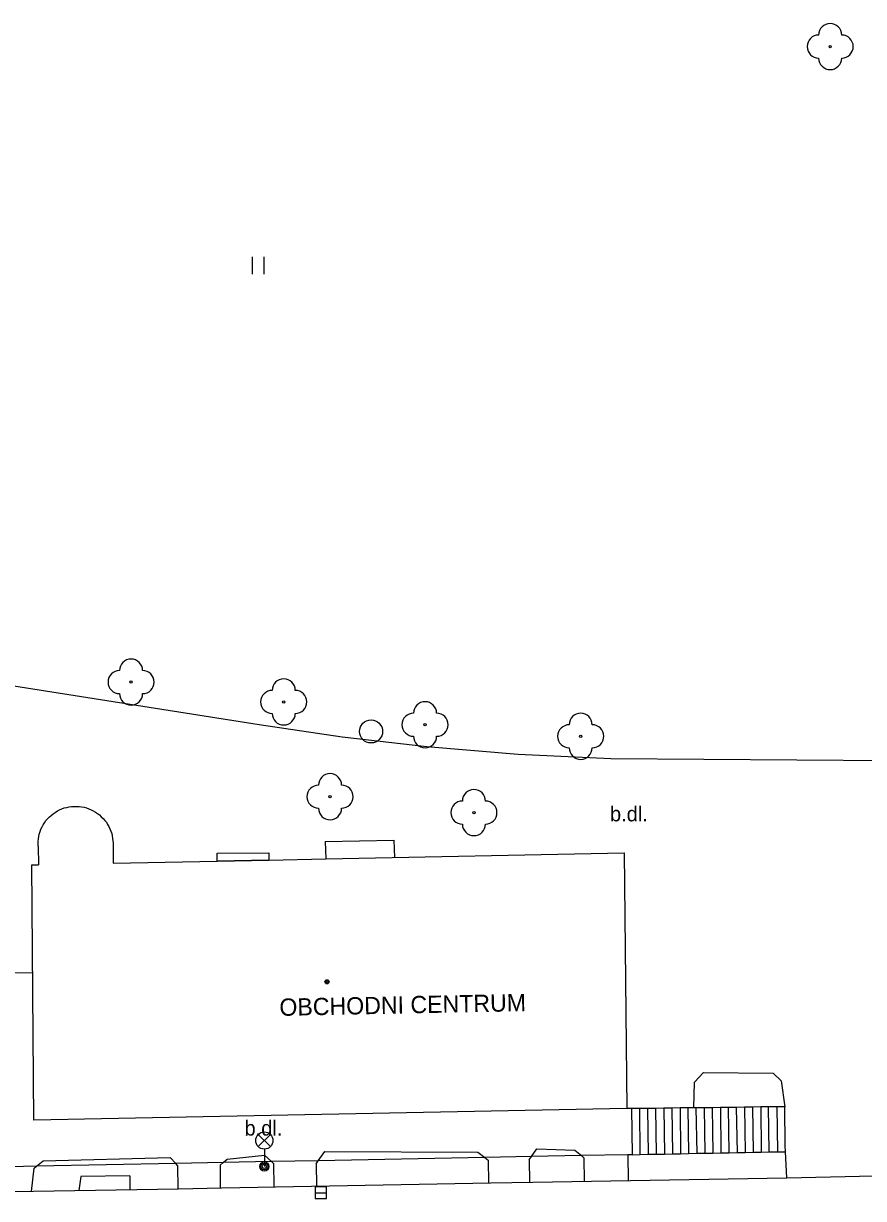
# Model space of a CAD drawing. Extents: x -641829 to -641525, y -1114855 to -1114359.
# Drawn here: x -641633.2 to -641596.7, y -1114670.9 to -1114619.9 of the extents above; entities that cross this region are included whole.
import ezdxf

# ---------------------------------------------------------------- set-up
doc = ezdxf.new("R2010")
doc.units = 0
for name, color, linetype in [('Vrstva 11', 7, 'Continuous'), ('Vrstva 22', 7, 'Continuous'), ('Vrstva 24', 7, 'Continuous'), ('Vrstva 27', 7, 'Continuous'), ('Vrstva 33', 7, 'Continuous'), ('Vrstva 36', 7, 'Continuous'), ('Vrstva 39', 7, 'Continuous'), ('Vrstva 40', 7, 'Continuous'), ('Vrstva 41', 7, 'Continuous'), ('Vrstva 5', 7, 'Continuous')]:
    doc.layers.add(name, color=color, linetype=linetype)

msp = doc.modelspace()

# ---------------------------------------------------------------- linework, layer by layer
at = {"layer": 'Vrstva 11'}
for p, q in [((-641622.94, -1114650.3), (-641619.35, -1114650.84)), ((-641619.35, -1114650.84), (-641615.67, -1114651.25)), ((-641615.67, -1114651.25), (-641611.71, -1114651.59)), ((-641611.71, -1114651.59), (-641607.69, -1114651.77)), ((-641607.69, -1114651.77), (-641592.01, -1114651.88)), ((-641620.08, -1114655.37), (-641617.1, -1114655.32)), ((-641620.08, -1114655.37), (-641620.06, -1114656.13)), ((-641617.1, -1114655.32), (-641617.08, -1114656.07)), ((-641635.07, -1114661.08), (-641632.77, -1114661.06)), ((-641604.06, -1114665.81), (-641603.67, -1114665.39)), ((-641603.67, -1114665.39), (-641600.65, -1114665.42)), ((-641600.65, -1114665.42), (-641600.31, -1114665.76)), ((-641604.09, -1114666.93), (-641604.06, -1114665.81)), ((-641600.31, -1114665.76), (-641600.15, -1114666.88)), ((-641606.79, -1114666.96), (-641607, -1114666.96)), ((-641606.44, -1114666.95), (-641606.79, -1114666.96)), ((-641606.79, -1114666.96), (-641606.77, -1114668.96)), ((-641606.42, -1114668.95), (-641606.44, -1114666.95)), ((-641606.1, -1114666.95), (-641606.44, -1114666.95)), ((-641606.1, -1114666.95), (-641606.07, -1114668.94)), ((-641605.75, -1114666.95), (-641606.1, -1114666.95)), ((-641605.4, -1114666.94), (-641605.75, -1114666.95)), ((-641605.75, -1114666.95), (-641605.72, -1114668.94)), ((-641605.4, -1114666.94), (-641605.37, -1114668.93)), ((-641605.05, -1114666.94), (-641605.4, -1114666.94)), ((-641604.69, -1114666.93), (-641605.05, -1114666.94)), ((-641605.05, -1114666.94), (-641605.02, -1114668.92)), ((-641604.69, -1114666.93), (-641604.67, -1114668.92)), ((-641604.35, -1114666.93), (-641604.69, -1114666.93)), ((-641604.35, -1114666.93), (-641604.32, -1114668.91)), ((-641604.09, -1114666.93), (-641604.35, -1114666.93)), ((-641604, -1114666.93), (-641604.09, -1114666.93)), ((-641603.65, -1114666.92), (-641604, -1114666.93)), ((-641604, -1114666.93), (-641603.97, -1114668.9)), ((-641603.65, -1114666.92), (-641603.62, -1114668.9)), ((-641603.3, -1114666.92), (-641603.65, -1114666.92)), ((-641602.94, -1114666.91), (-641603.3, -1114666.92)), ((-641603.3, -1114666.92), (-641603.27, -1114668.89)), ((-641602.94, -1114666.91), (-641602.92, -1114668.88)), ((-641602.6, -1114666.91), (-641602.94, -1114666.91)), ((-641602.6, -1114666.91), (-641602.57, -1114668.88)), ((-641602.25, -1114666.91), (-641602.6, -1114666.91)), ((-641601.9, -1114666.9), (-641602.25, -1114666.91)), ((-641602.25, -1114666.91), (-641602.22, -1114668.87)), ((-641601.9, -1114666.9), (-641601.87, -1114668.86)), ((-641601.55, -1114666.9), (-641601.9, -1114666.9)), ((-641601.19, -1114666.89), (-641601.55, -1114666.9)), ((-641601.55, -1114666.9), (-641601.52, -1114668.85)), ((-641601.19, -1114666.89), (-641601.17, -1114668.85)), ((-641600.85, -1114666.89), (-641601.19, -1114666.89)), ((-641600.82, -1114668.84), (-641600.85, -1114666.89)), ((-641600.5, -1114666.89), (-641600.85, -1114666.89)), ((-641600.15, -1114666.88), (-641600.5, -1114666.89)), ((-641600.5, -1114666.89), (-641600.47, -1114668.83)), ((-641600.13, -1114668.58), (-641600.15, -1114666.88)), ((-641624.33, -1114669.15), (-641622.72, -1114668.98)), ((-641622.72, -1114668.98), (-641622.41, -1114669.26)), ((-641620.38, -1114669.22), (-641620.09, -1114668.82)), ((-641620.09, -1114668.82), (-641613.46, -1114668.85)), ((-641613.46, -1114668.85), (-641613.16, -1114669.08)), ((-641611.14, -1114669.04), (-641613.16, -1114669.08)), ((-641611.23, -1114669.18), (-641611.14, -1114669.04)), ((-641611.14, -1114669.04), (-641610.9, -1114668.7)), ((-641608.97, -1114669), (-641611.14, -1114669.04)), ((-641610.9, -1114668.7), (-641609.26, -1114668.77)), ((-641609.26, -1114668.77), (-641608.97, -1114669)), ((-641606.96, -1114668.96), (-641608.97, -1114669)), ((-641608.97, -1114669), (-641608.86, -1114669.09)), ((-641606.77, -1114668.96), (-641606.96, -1114668.96)), ((-641606.96, -1114668.96), (-641606.94, -1114670.08)), ((-641606.77, -1114668.96), (-641606.42, -1114668.95)), ((-641606.42, -1114668.95), (-641606.07, -1114668.94)), ((-641606.07, -1114668.94), (-641605.72, -1114668.94)), ((-641605.72, -1114668.94), (-641605.37, -1114668.93)), ((-641605.37, -1114668.93), (-641605.02, -1114668.92)), ((-641605.02, -1114668.92), (-641604.67, -1114668.92)), ((-641604.67, -1114668.92), (-641604.32, -1114668.91)), ((-641604.32, -1114668.91), (-641603.97, -1114668.9)), ((-641603.97, -1114668.9), (-641603.62, -1114668.9)), ((-641603.62, -1114668.9), (-641603.27, -1114668.89)), ((-641603.27, -1114668.89), (-641602.92, -1114668.88)), ((-641602.92, -1114668.88), (-641602.57, -1114668.88)), ((-641602.57, -1114668.88), (-641602.22, -1114668.87)), ((-641602.22, -1114668.87), (-641601.87, -1114668.86)), ((-641601.87, -1114668.86), (-641601.52, -1114668.85)), ((-641601.52, -1114668.85), (-641601.17, -1114668.85)), ((-641601.17, -1114668.85), (-641600.82, -1114668.84)), ((-641600.82, -1114668.84), (-641600.47, -1114668.83)), ((-641600.47, -1114668.83), (-641600.12, -1114668.83)), ((-641600.12, -1114668.83), (-641600.13, -1114668.58)), ((-641600.06, -1114669.96), (-641600.12, -1114668.83)), ((-641632.6, -1114669.46), (-641635, -1114669.51)), ((-641632.82, -1114670.55), (-641632.7, -1114669.54)), ((-641632.7, -1114669.54), (-641632.6, -1114669.46)), ((-641632.6, -1114669.46), (-641632.31, -1114669.23)), ((-641626.56, -1114669.34), (-641632.6, -1114669.46)), ((-641632.31, -1114669.23), (-641626.81, -1114669.08)), ((-641626.56, -1114669.34), (-641626.81, -1114669.08)), ((-641624.51, -1114669.3), (-641626.56, -1114669.34)), ((-641626.48, -1114669.43), (-641626.56, -1114669.34)), ((-641626.48, -1114669.43), (-641626.47, -1114670.44)), ((-641624.64, -1114669.41), (-641624.51, -1114669.3)), ((-641624.64, -1114669.41), (-641624.63, -1114670.4)), ((-641624.51, -1114669.3), (-641624.33, -1114669.15)), ((-641622.41, -1114669.26), (-641624.51, -1114669.3)), ((-641620.38, -1114669.22), (-641622.41, -1114669.26)), ((-641622.41, -1114669.26), (-641622.32, -1114669.34)), ((-641622.32, -1114669.34), (-641622.31, -1114670.36)), ((-641620.47, -1114669.35), (-641620.38, -1114669.22)), ((-641620.47, -1114669.35), (-641620.46, -1114670.32)), ((-641613.16, -1114669.08), (-641620.38, -1114669.22)), ((-641613.16, -1114669.08), (-641613.01, -1114669.2)), ((-641613.01, -1114669.2), (-641613, -1114670.18)), ((-641611.23, -1114669.18), (-641611.22, -1114670.15)), ((-641608.86, -1114669.09), (-641608.85, -1114670.11)), ((-641630.68, -1114669.9), (-641630.76, -1114670.51)), ((-641628.56, -1114669.87), (-641630.68, -1114669.9)), ((-641628.56, -1114669.87), (-641628.55, -1114670.48)), ((-641611.08, -1114670.15), (-641600.06, -1114669.96)), ((-641600.06, -1114669.96), (-641596.27, -1114669.88)), ((-641633.63, -1114670.56), (-641626.46, -1114670.44)), ((-641626.46, -1114670.44), (-641624.56, -1114670.4)), ((-641624.56, -1114670.4), (-641612.89, -1114670.18)), ((-641612.89, -1114670.18), (-641611.08, -1114670.15))]:
    msp.add_line(p, q, dxfattribs=at)
msp.add_lwpolyline([(-641647.34, -1114646.45), (-641638.29, -1114647.88), (-641635.16, -1114648.37), (-641622.94, -1114650.3)], dxfattribs=at)
at = {"layer": 'Vrstva 22'}
for centre in [(-641598.18, -1114620.89), (-641628.5, -1114648.46), (-641621.88, -1114649.32), (-641615.75, -1114650.31), (-641609, -1114650.81), (-641619.87, -1114653.43), (-641613.63, -1114654.12)]:
    msp.add_circle(centre, 0.05, dxfattribs=at)
for centre, start, end in [((-641598.18, -1114620.39), 0, 180), ((-641598.68, -1114620.89), 90, 270), ((-641597.68, -1114620.89), 270, 90), ((-641598.18, -1114621.39), 180, 0), ((-641628.5, -1114647.96), 0, 180), ((-641629, -1114648.46), 90, 270), ((-641628, -1114648.46), 270, 90), ((-641621.88, -1114648.82), 0, 180), ((-641628.5, -1114648.96), 180, 0), ((-641622.38, -1114649.32), 90, 270), ((-641621.38, -1114649.32), 270, 90), ((-641615.75, -1114649.81), 0, 180), ((-641621.88, -1114649.82), 180, 0), ((-641616.25, -1114650.31), 90, 270), ((-641615.25, -1114650.31), 270, 90), ((-641609, -1114650.31), 0, 180), ((-641609.5, -1114650.81), 90, 270), ((-641608.5, -1114650.81), 270, 90), ((-641615.75, -1114650.81), 180, 0), ((-641609, -1114651.31), 180, 0), ((-641619.87, -1114652.93), 0, 180), ((-641620.37, -1114653.43), 90, 270), ((-641619.37, -1114653.43), 270, 90), ((-641613.63, -1114653.62), 0, 180), ((-641614.13, -1114654.12), 90, 270), ((-641613.13, -1114654.12), 270, 90), ((-641619.87, -1114653.93), 180, 0), ((-641613.63, -1114654.62), 180, 0)]:
    msp.add_arc(centre, 0.5, start, end, dxfattribs=at)
at = {"layer": 'Vrstva 24'}
msp.add_lwpolyline([(-641624.77, -1114655.88), (-641622.53, -1114655.87), (-641622.53, -1114656.18), (-641624.77, -1114656.23), (-641624.77, -1114655.88)], dxfattribs=at)
at = {"layer": 'Vrstva 27'}
msp.add_line((-641620.52, -1114670.61), (-641620.02, -1114670.61), dxfattribs=at)
msp.add_lwpolyline([(-641620.52, -1114670.86), (-641620.02, -1114670.86), (-641620.02, -1114670.36), (-641620.52, -1114670.36)], close=True, dxfattribs=at)
msp.add_circle((-641618.09, -1114650.6), 0.5, dxfattribs=at)
at = {"layer": 'Vrstva 33'}
for p, q in [((-641622.984, -1114668.61), (-641622.456, -1114668.08)), ((-641622.984, -1114668.08), (-641622.456, -1114668.61)), ((-641622.72, -1114668.72), (-641622.72, -1114669.47))]:
    msp.add_line(p, q, dxfattribs=at)
for centre, radius in [((-641622.72, -1114668.345), 0.375), ((-641622.72, -1114669.47), 0.2), ((-641622.72, -1114669.47), 0.145), ((-641622.72, -1114669.47), 0.0876)]:
    msp.add_circle(centre, radius, dxfattribs=at)
at = {"layer": 'Vrstva 36'}
for p, q in [((-641623.234, -1114630.762), (-641623.234, -1114630.014)), ((-641622.734, -1114630.762), (-641622.734, -1114630.014))]:
    msp.add_line(p, q, dxfattribs=at)
at = {"layer": 'Vrstva 39'}
for radius in [0.09, 0.0398]:
    msp.add_circle((-641620, -1114661.46), radius, dxfattribs=at)
at = {"layer": 'Vrstva 5'}
for p, q in [((-641632.04, -1114654.31), (-641631.96, -1114654.24)), ((-641631.96, -1114654.24), (-641631.88, -1114654.17)), ((-641631.88, -1114654.17), (-641631.79, -1114654.11)), ((-641631.79, -1114654.11), (-641631.69, -1114654.05)), ((-641631.69, -1114654.05), (-641631.6, -1114654)), ((-641631.6, -1114654), (-641631.5, -1114653.96)), ((-641631.5, -1114653.96), (-641631.4, -1114653.92)), ((-641631.4, -1114653.92), (-641631.29, -1114653.9)), ((-641631.29, -1114653.9), (-641631.19, -1114653.87)), ((-641631.19, -1114653.87), (-641631.08, -1114653.86)), ((-641631.08, -1114653.86), (-641630.97, -1114653.85)), ((-641630.97, -1114653.85), (-641630.86, -1114653.85)), ((-641630.86, -1114653.85), (-641630.75, -1114653.86)), ((-641630.75, -1114653.86), (-641630.65, -1114653.87)), ((-641630.65, -1114653.87), (-641630.54, -1114653.89)), ((-641630.54, -1114653.89), (-641630.44, -1114653.92)), ((-641630.44, -1114653.92), (-641630.33, -1114653.95)), ((-641630.33, -1114653.95), (-641630.23, -1114654)), ((-641630.23, -1114654), (-641630.14, -1114654.04)), ((-641630.14, -1114654.04), (-641630.04, -1114654.1)), ((-641630.04, -1114654.1), (-641629.95, -1114654.16)), ((-641629.95, -1114654.16), (-641629.87, -1114654.22)), ((-641629.87, -1114654.22), (-641629.79, -1114654.3)), ((-641632.41, -1114654.84), (-641632.36, -1114654.74)), ((-641632.36, -1114654.74), (-641632.31, -1114654.65)), ((-641632.31, -1114654.65), (-641632.25, -1114654.56)), ((-641632.25, -1114654.56), (-641632.19, -1114654.47)), ((-641632.19, -1114654.47), (-641632.12, -1114654.39)), ((-641632.12, -1114654.39), (-641632.04, -1114654.31)), ((-641629.79, -1114654.3), (-641629.71, -1114654.37)), ((-641629.71, -1114654.37), (-641629.64, -1114654.46)), ((-641629.64, -1114654.46), (-641629.57, -1114654.54)), ((-641629.57, -1114654.54), (-641629.52, -1114654.63)), ((-641629.52, -1114654.63), (-641629.46, -1114654.73)), ((-641629.46, -1114654.73), (-641629.42, -1114654.82)), ((-641632.53, -1114655.37), (-641632.52, -1114655.26)), ((-641632.52, -1114655.26), (-641632.5, -1114655.15)), ((-641632.5, -1114655.15), (-641632.48, -1114655.05)), ((-641632.48, -1114655.05), (-641632.44, -1114654.94)), ((-641632.44, -1114654.94), (-641632.41, -1114654.84)), ((-641629.42, -1114654.82), (-641629.38, -1114654.92)), ((-641629.38, -1114654.92), (-641629.34, -1114655.03)), ((-641629.34, -1114655.03), (-641629.32, -1114655.13)), ((-641629.32, -1114655.13), (-641629.3, -1114655.24)), ((-641629.3, -1114655.24), (-641629.29, -1114655.35)), ((-641632.53, -1114655.47), (-641632.53, -1114655.37)), ((-641632.53, -1114655.58), (-641632.53, -1114655.47)), ((-641632.53, -1114655.58), (-641632.51, -1114656.38)), ((-641629.29, -1114655.35), (-641629.28, -1114655.45)), ((-641629.28, -1114655.45), (-641629.28, -1114655.52)), ((-641629.28, -1114655.52), (-641629.27, -1114656.32)), ((-641620.06, -1114656.13), (-641607.12, -1114655.87)), ((-641607.12, -1114655.87), (-641607, -1114666.96)), ((-641632.81, -1114656.39), (-641632.51, -1114656.38)), ((-641632.72, -1114667.46), (-641632.81, -1114656.39)), ((-641607, -1114666.96), (-641632.72, -1114667.46))]:
    msp.add_line(p, q, dxfattribs=at)
msp.add_lwpolyline([(-641629.27, -1114656.32), (-641624.77, -1114656.23), (-641622.53, -1114656.18), (-641620.06, -1114656.13)], dxfattribs=at)

# ---------------------------------------------------------------- texts
at = {"layer": 'Vrstva 40'}
for p in [(-641607.73, -1114654.5), (-641623.58, -1114668.13)]:
    msp.add_text('b.dl. ', height=0.65, dxfattribs=at).set_placement(p)
at = {"layer": 'Vrstva 41'}
msp.add_text('OBCHODNI CENTRUM', height=0.7499, rotation=1.1159, dxfattribs=at).set_placement((-641622.06, -1114662.94))

doc.saveas('drawing.dxf')
